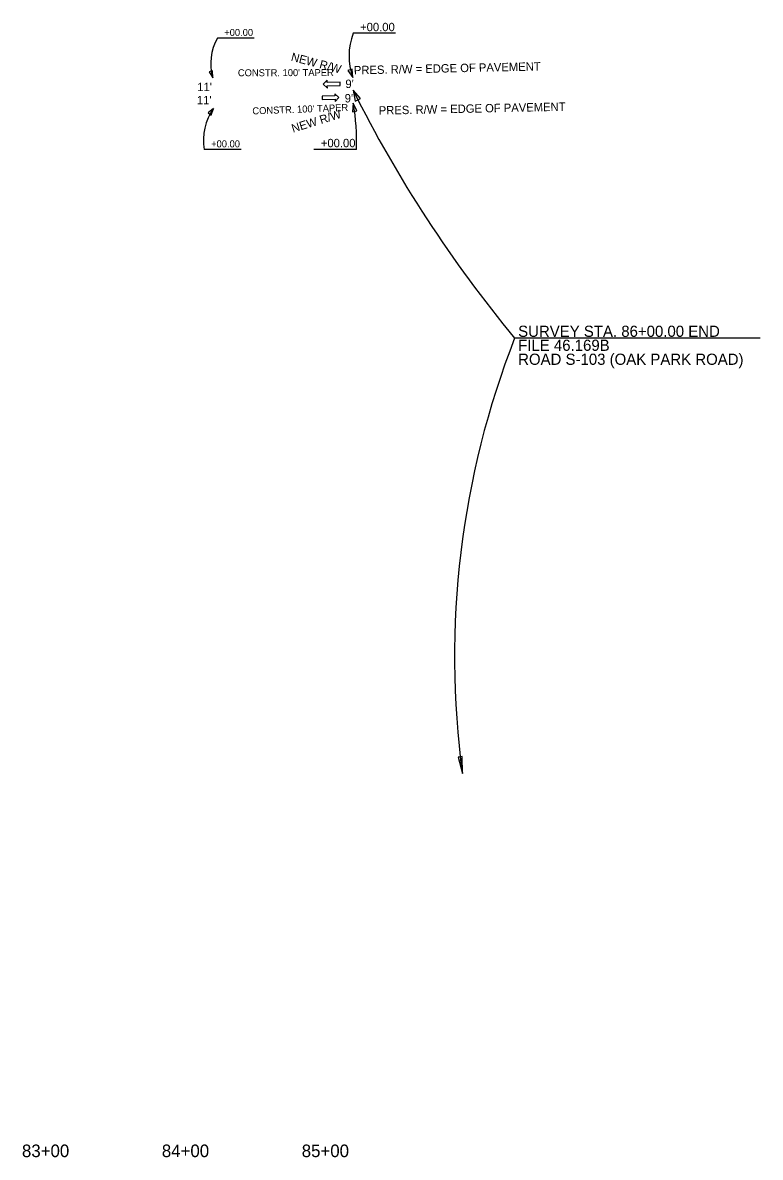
# Model space of a CAD drawing. Extents: x 1964377 to 1966966, y 1116414 to 1123213.
# Drawn here: x 1965757 to 1966284, y 1119864 to 1120675 of the extents above; entities that cross this region are included whole.
import ezdxf

# ---------------------------------------------------------------- set-up
doc = ezdxf.new("R2010")
doc.units = 0
for name, color, linetype in [('RD_DDB_StaTX', 7, 'Continuous'), ('RD_EX_RW_TX', 7, 'Continuous'), ('RD_PD_Final_LnLine', 7, 'Continuous'), ('RD_PD_Final_TX', 7, 'Continuous'), ('RD_PD_RW_TX', 7, 'Continuous')]:
    doc.layers.add(name, color=color, linetype=linetype)

msp = doc.modelspace()

# ---------------------------------------------------------------- linework, layer by layer
at = {"layer": 'RD_PD_Final_LnLine'}
for points in [[(1965984.07, 1120630.18), (1965984.02, 1120632.58), (1965974.85, 1120632.39), (1965974.82, 1120634.01), (1965972.05, 1120631.13), (1965974.93, 1120628.36), (1965974.9, 1120629.99)], [(1965971.21, 1120622.54), (1965971.26, 1120620.14), (1965980.43, 1120620.33), (1965980.46, 1120618.71), (1965983.23, 1120621.59), (1965980.34, 1120624.36), (1965980.38, 1120622.73)]]:
    msp.add_lwpolyline(points, close=True, dxfattribs=at)
at = {"layer": 'RD_PD_Final_TX'}
for p, q in [((1965922.62, 1120664.15), (1965896.33, 1120664.15)), ((1965913.25, 1120584.5), (1965886.96, 1120584.5)), ((1966284.43, 1120449.5), (1966108.83, 1120449.5)), ((1966071.33, 1120150.42), (1966068.35, 1120150.01)), ((1966068.35, 1120150.01), (1966071.45, 1120138.32)), ((1966071.45, 1120138.32), (1966071.33, 1120150.42))]:
    msp.add_line(p, q, dxfattribs=at)
for points in [[(1965890.46, 1120640.02), (1965893.08, 1120635.76), (1965892.94, 1120640.75)], [(1965998.6, 1120620.86), (1965993.29, 1120626.85), (1965994.89, 1120619.01)], [(1965891.8, 1120609.07), (1965893.54, 1120613.76), (1965889.69, 1120610.57)]]:
    msp.add_lwpolyline(points, close=True, dxfattribs=at)
for centre, radius, start, end in [((1965928.02, 1120646.14), 36.45, 150.38875, 196.55433), ((1966829.52, 1121045.36), 935.12, 206.58673, 219.58341), ((1965925.22, 1120591.27), 38.85, 144.6313, 190.03781), ((1966690.26, 1120221.82), 624.42, 158.61502, 187.68431)]:
    msp.add_arc(centre, radius, start, end, dxfattribs=at)
at = {"layer": 'RD_PD_RW_TX'}
for p, q in [((1966023.72, 1120667.53), (1965993.36, 1120667.53)), ((1965995.66, 1120584.57), (1965965.29, 1120584.57))]:
    msp.add_line(p, q, dxfattribs=at)
for points in [[(1965989.68, 1120640.92), (1965993.09, 1120635.99), (1965992.61, 1120641.97)], [(1965996.04, 1120612.05), (1965993.48, 1120617.48), (1965992.99, 1120611.5)]]:
    msp.add_lwpolyline(points, close=True, dxfattribs=at)
for centre, radius, start, end in [((1966036.24, 1120651.4), 45.81, 159.38614, 199.66211), ((1965849.79, 1120591.43), 146.03, 357.30547, 10.27423)]:
    msp.add_arc(centre, radius, start, end, dxfattribs=at)

# ---------------------------------------------------------------- texts
at = {"layer": 'RD_DDB_StaTX'}
for s, p in [('83+00', (1965756.62, 1119864.05)), ('84+00', (1965856.62, 1119864.05)), ('85+00', (1965956.62, 1119864.05))]:
    msp.add_text(s, height=9, dxfattribs=at).set_placement(p)
at = {"layer": 'RD_EX_RW_TX'}
for p in [(1965993.95, 1120638.14), (1966011.75, 1120609.36)]:
    msp.add_text('PRES. R/W = EDGE OF PAVEMENT', height=6, rotation=1.19619, dxfattribs=at).set_placement(p)
at = {"layer": 'RD_PD_Final_TX'}
for s, height, p in [('+00.00', 5, (1965901.21, 1120665.65)), ("11'", 6, (1965881.94, 1120626.18)), ("9'", 6, (1965987.83, 1120628.42)), ("11'", 6, (1965881.65, 1120616.74)), ("9'", 6, (1965987.34, 1120618.11)), ('+00.00', 5, (1965891.84, 1120586)), ('SURVEY STA. 86+00.00 END', 8, (1966111.33, 1120450.5)), ('FILE 46.169B', 8, (1966111.33, 1120440.5)), ('ROAD S-103 (OAK PARK ROAD)', 8, (1966111.33, 1120430.5))]:
    msp.add_text(s, height=height, dxfattribs=at).set_placement(p)
for rotation, p in [(0.13216, (1965910.99, 1120636.82)), (2.1293, (1965921.41, 1120609.52))]:
    msp.add_text("CONSTR. 100' TAPER", height=5, rotation=rotation, dxfattribs=at).set_placement(p)
at = {"layer": 'RD_PD_RW_TX'}
for p in [(1965998.36, 1120669.03), (1965970.29, 1120586.07)]:
    msp.add_text('+00.00', height=6, dxfattribs=at).set_placement(p)
for rotation, p in [(345.36181, (1965948.55, 1120648.03)), (17.13477, (1965950.4, 1120596.47))]:
    msp.add_text('NEW R/W', height=6, rotation=rotation, dxfattribs=at).set_placement(p)

doc.saveas('drawing.dxf')
